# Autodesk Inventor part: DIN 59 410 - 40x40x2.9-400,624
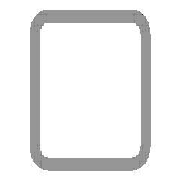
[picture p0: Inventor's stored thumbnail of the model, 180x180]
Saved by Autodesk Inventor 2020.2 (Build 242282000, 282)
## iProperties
Manager: www.cadconsulting.pl
Company: Fabian Stasiak CAD Consulting
_CCFamilyMember: 10
_CCFamilyDisplayName: DIN 59410 (Kwadrat) - Rurki stalowe o przekroju kwadratowym formowane na gorąco
_FrameMemberDoc: Frame Member File
_Version: 15.0.0
_GetPNFromCC: 1
Created: 2015-01
Part Number: DIN 59 410 - 40x40x2.9-400,624
Material: Stal, miękka
Description: Rurki stalowe o przekroju kwadratowym formowane na gorąco
Document SubType Name: Modellieren
Standard: DIN
Designer: F.Stasiak
Standards Organization: DIN
Language: pl-PL
Size Designation: 40x40x2.9
Categories: <MemberInstance><Categories><Category DisplayName="Kształtowniki konstrukcyjne" InternalName="089c4875-fa83-4c05-b084-43b9cc11f5ed" Mnemonic="GRDR"><CategoryPar
Stock Number: 40x40x2.9
Density: 7.85 g/cm^3
Appearance: Częściowo polerowana
Mass: 1157 g
Surface Area: 1028.03 cm^2
Volume: 147.388 cm^3
Catalog Web Link: www.expertbooks.pl
IsCustomPart: 1
G_W: 40,000 mm
G_H: 40,000 mm
+458A8CE7-21F4-40B2-BEC4-E0B2FA03ADB0+CUTDETAIL1: Wytnij
+8C111B0A-0D8E-47BD-820E-77E07AE6364C+CUTDETAIL2: Wytnij
G_L: 400,624 mm
Author: F.Stasiak
Subject: Zbiór ćwiczeń. Autodesk Inventor 2020. Kurs Professional
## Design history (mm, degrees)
node "Płaszczyzna początkowa"
node "Płaszczyzna końcowa"
sketch "Szkic"
  geometry: L1 (-14.2, 20)-(14.2, 20); L2 (20, 14.2)-(20, -14.2); L3 (14.2, -20)-(-14.2, -20); L4 (-20, -14.2)-(-20, 14.2); L5 (-29.682, 0)-(29.682, 0) reference; L6 (0, -29.682)-(0, 29.682) reference; L7 (-14.2, 17.1)-(14.2, 17.1); L8 (17.1, 14.2)-(17.1, -14.2); L9 (14.2, -17.1)-(-14.2, -17.1); L10 (-17.1, -14.2)-(-17.1, 14.2); A1 r 5.8 centre (-14.2, 14.2) between (-14.2, 20) and (-20, 14.2); A2 r 5.8 centre (14.2, 14.2) between (20, 14.2) and (14.2, 20); A3 r 5.8 centre (14.2, -14.2) between (14.2, -20) and (20, -14.2); A4 r 5.8 centre (-14.2, -14.2) between (-20, -14.2) and (-14.2, -20); A5 r 2.9 centre (-14.2, 14.2) between (-14.2, 17.1) and (-17.1, 14.2); A6 r 2.9 centre (14.2, 14.2) between (17.1, 14.2) and (14.2, 17.1); A7 r 2.9 centre (14.2, -14.2) between (14.2, -17.1) and (17.1, -14.2); A8 r 2.9 centre (-14.2, -14.2) between (-17.1, -14.2) and (-14.2, -17.1); 3 further points
  constraints: 16 end point, 16 point on circle, 8 centre point, 8 tangent, 6 point on line, 4 parallel, 3 equal radius, 3 perpendicular, 1 horizontal, 7 other
  dimensions: "b" = 40 distance of point (-20, 20) point (20, 20); "msp_r" = 5.8 radius of A1 (= 2 x ParT); "d8" = 20 distance between parallel lines of L4 L6 (= d9); "d9" = 20 distance between parallel lines of L3 L5 (= 0.5 x b); "d10" = 2.9 distance between parallel lines of L3 L9 (= ParT)
extrude "Bryła" new body sketch "Szkic" taper "d4" = 0 deg; stored distance "NLG" = 10
node "Driven Length"
  sketch "Sketch2"
    geometry: L1 (0, 0)-(10, 0) reference
    constraints: 2 end point, 1 horizontal
  workplane "Work Plane3"
  sketch "Sketch3"
    geometry: L1 (-2, 8.284)-(12, 8.284) reference; L2 (-2, 408.909)-(12, 408.909) reference
    dimensions: "d14" = 400.62446 distance between parallel lines of L1 L2 (derived)
node "Płaszczyzna konstrukcyjna4"
feature "Podział1"
node "Płaszczyzna konstrukcyjna5"
feature "Podział2"
body "Solid1"
other parameters: "ParT" = 2.9, "G_OFFSET_START" = -8.28427 [user parameter; used in 1 equation term], "G_OFFSET_END" = -15.35534 [user parameter; used in 1 equation term], "d11" = 8.28427 (= -G_OFFSET_START), "d12" = 408.90873 (= G_OFFSET_END + B_L), "G_L" = 400.62446 (= d14) [user parameter], "B_L" = 424.26407 [user parameter; used in 1 equation term], "d13" = 90 deg
